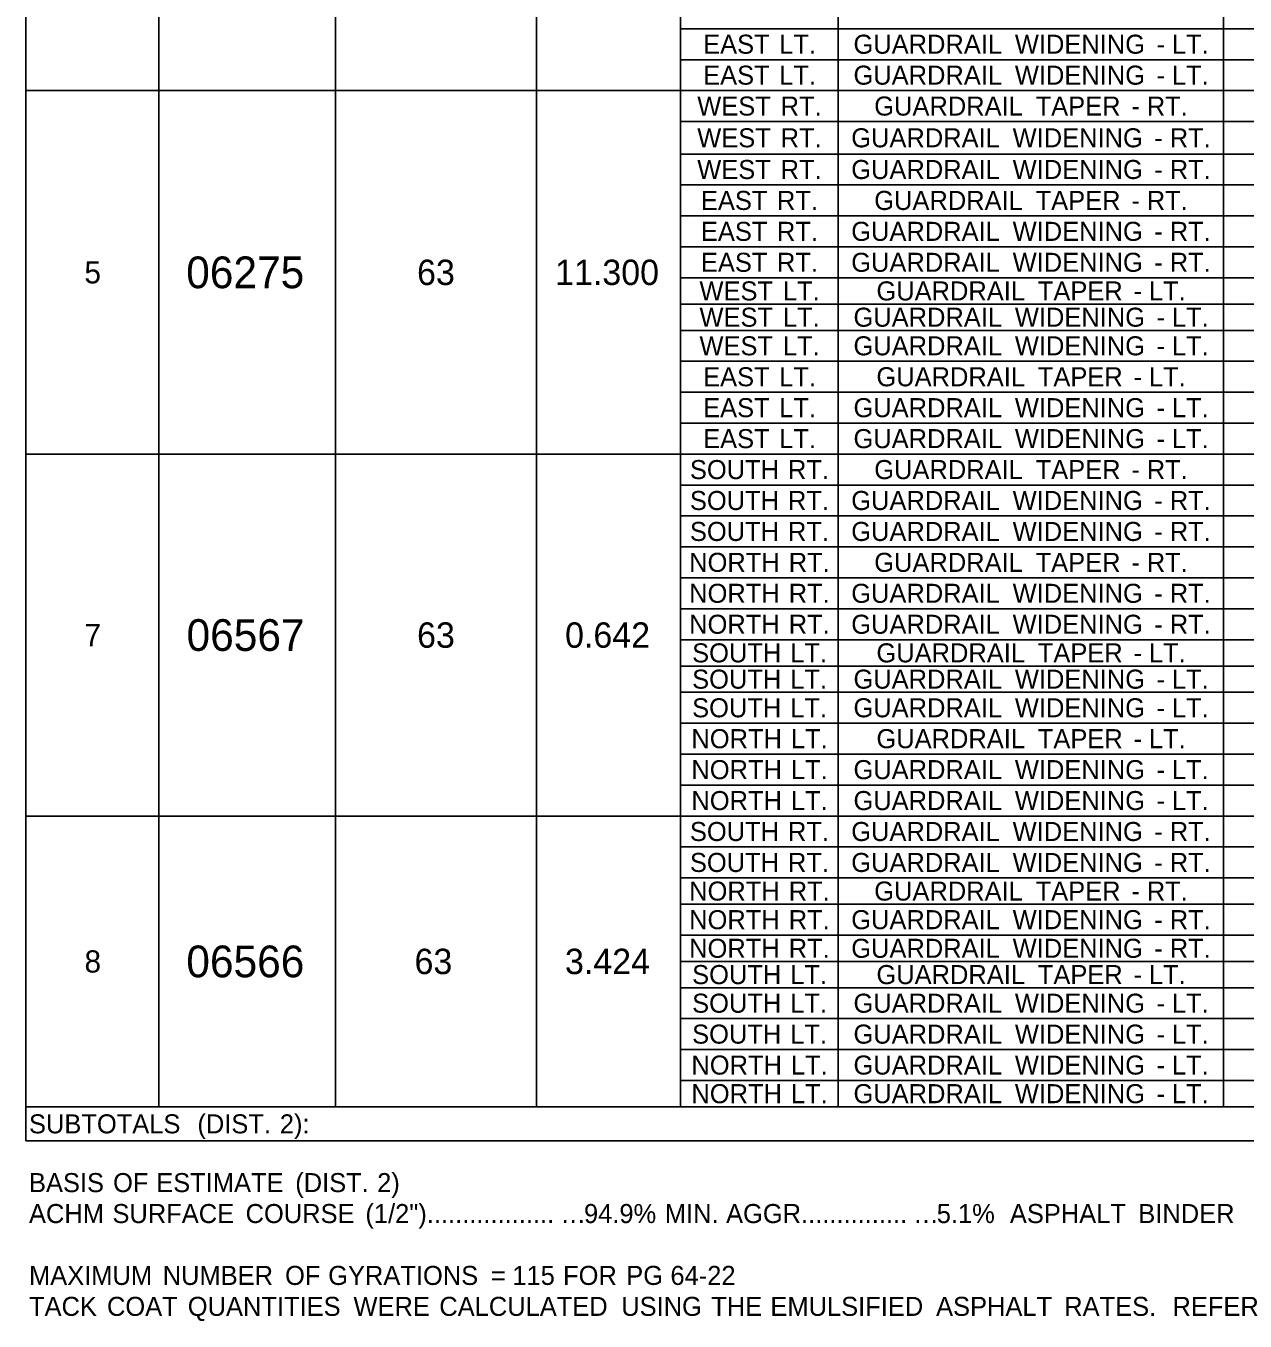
# Model space of a CAD drawing. Extents: x 544250 to 1930787, y -1948365 to 596640.
# Drawn here: x 555672.1 to 556001.3, y -1946822.7 to -1946472.9 of the extents above; entities that cross this region are included whole.
import ezdxf

# ---------------------------------------------------------------- set-up
doc = ezdxf.new("R2010")
doc.units = 0
doc.layers.add('Default', color=7, linetype='Continuous')

msp = doc.modelspace()

# ---------------------------------------------------------------- linework, layer by layer
at = {"layer": 'Default'}
for p, q in [((555672.13, -1946774.02), (555672.13, -1946131.03)), ((555708.06, -1946764.83), (555708.06, -1946131.03)), ((555755.69, -1946764.83), (555755.69, -1946131.03)), ((555810, -1946764.83), (555810, -1946131.03)), ((555848.86, -1946764.83), (555848.86, -1946131.03)), ((555891.47, -1946764.83), (555891.47, -1946131.03)), ((555995.5, -1946764.83), (555995.5, -1946131.03)), ((555848.86, -1946473.62), (556257.47, -1946473.62)), ((555848.86, -1946481.98), (556257.47, -1946481.98)), ((555672.13, -1946490.33), (556257.47, -1946490.33)), ((555848.86, -1946498.69), (556257.47, -1946498.69)), ((555848.86, -1946507.46), (556257.47, -1946507.46)), ((555848.86, -1946515.82), (556257.47, -1946515.82)), ((555848.86, -1946524.18), (556257.47, -1946524.18)), ((555848.86, -1946532.53), (556257.47, -1946532.53)), ((555848.86, -1946540.89), (556257.47, -1946540.89)), ((555848.86, -1946547.99), (556257.47, -1946547.99)), ((555848.86, -1946555.09), (556257.47, -1946555.09)), ((555848.86, -1946563.45), (556257.47, -1946563.45)), ((555848.86, -1946571.8), (556257.47, -1946571.8)), ((555848.86, -1946580.16), (556257.47, -1946580.16)), ((555672.13, -1946588.52), (556257.47, -1946588.52)), ((555848.86, -1946596.87), (556257.47, -1946596.87)), ((555848.86, -1946605.23), (556257.47, -1946605.23)), ((555848.86, -1946613.59), (556257.47, -1946613.59)), ((555848.86, -1946621.94), (556257.47, -1946621.94)), ((555848.86, -1946630.3), (556257.47, -1946630.3)), ((555848.86, -1946638.65), (556257.47, -1946638.65)), ((555848.86, -1946645.76), (556257.47, -1946645.76)), ((555848.86, -1946652.86), (556257.47, -1946652.86)), ((555848.86, -1946661.21), (556257.47, -1946661.21)), ((555848.86, -1946669.57), (556257.47, -1946669.57)), ((555848.86, -1946677.93), (556257.47, -1946677.93)), ((555672.13, -1946686.28), (556257.47, -1946686.28)), ((555848.86, -1946686.28), (556257.47, -1946686.28)), ((555848.86, -1946694.64), (556257.47, -1946694.64)), ((555848.86, -1946702.99), (556257.47, -1946702.99)), ((555848.86, -1946710.1), (556257.47, -1946710.1)), ((555848.86, -1946718.45), (556257.47, -1946718.45)), ((555848.86, -1946725.56), (556257.47, -1946725.56)), ((555848.86, -1946732.66), (556257.47, -1946732.66)), ((555848.86, -1946741.01), (556257.47, -1946741.01)), ((555848.86, -1946749.37), (556257.47, -1946749.37)), ((555848.86, -1946757.73), (556257.47, -1946757.73)), ((555672.13, -1946764.83), (556257.47, -1946764.83)), ((555672.13, -1946774.02), (556257.47, -1946774.02))]:
    msp.add_line(p, q, dxfattribs=at)

# ---------------------------------------------------------------- texts
for s, height, p in [('EAST', 5.142, (555854.98, -1946480.37)), (' LT.', 5.142, (555873.6, -1946480.37)), ('GUARDRAIL', 5.142, (555895.57, -1946480.37)), (' WIDENING', 5.142, (555937.24, -1946480.37)), (' LT.', 5.142, (555979.66, -1946480.37)), (' -', 5.142, (555975.5, -1946480.37)), ('EAST', 5.142, (555854.98, -1946488.73)), (' LT.', 5.142, (555873.6, -1946488.73)), ('GUARDRAIL', 5.142, (555895.57, -1946488.73)), (' WIDENING', 5.142, (555937.24, -1946488.73)), (' LT.', 5.142, (555979.66, -1946488.73)), (' -', 5.142, (555975.5, -1946488.73)), ('WEST', 5.142, (555853.39, -1946497.08)), (' RT.', 5.142, (555874, -1946497.08)), ('GUARDRAIL', 5.142, (555901.18, -1946497.08)), (' TAPER', 5.142, (555942.84, -1946497.08)), (' -', 5.142, (555968.7, -1946497.08)), (' RT.', 5.142, (555972.86, -1946497.08)), ('WEST', 5.142, (555853.39, -1946505.65)), (' RT.', 5.142, (555874, -1946505.65)), ('GUARDRAIL', 5.142, (555894.97, -1946505.65)), (' WIDENING', 5.142, (555936.64, -1946505.65)), (' RT.', 5.142, (555979.06, -1946505.65)), (' -', 5.142, (555974.9, -1946505.65)), ('WEST', 5.142, (555853.39, -1946514.21)), (' RT.', 5.142, (555874, -1946514.21)), ('GUARDRAIL', 5.142, (555894.97, -1946514.21)), (' WIDENING', 5.142, (555936.64, -1946514.21)), (' RT.', 5.142, (555979.06, -1946514.21)), (' -', 5.142, (555974.9, -1946514.21)), ('EAST', 5.142, (555854.38, -1946522.57)), (' RT.', 5.142, (555873.01, -1946522.57)), ('GUARDRAIL', 5.142, (555901.18, -1946522.57)), (' TAPER', 5.142, (555942.84, -1946522.57)), (' RT.', 5.142, (555972.86, -1946522.57)), (' -', 5.142, (555968.7, -1946522.57)), ('EAST', 5.142, (555854.38, -1946530.92)), (' RT.', 5.142, (555873.01, -1946530.92)), ('GUARDRAIL', 5.142, (555894.97, -1946530.92)), (' WIDENING', 5.142, (555936.64, -1946530.92)), (' RT.', 5.142, (555979.06, -1946530.92)), (' -', 5.142, (555974.9, -1946530.92)), ('5', 6, (555687.93, -1946542.42)), ('06275', 8.57, (555715.41, -1946543.71)), ('63', 6.856, (555777.74, -1946542.85)), ('11.300', 6.856, (555815.02, -1946542.85)), ('EAST', 5.142, (555854.38, -1946539.28)), (' RT.', 5.142, (555873.01, -1946539.28)), ('GUARDRAIL', 5.142, (555894.97, -1946539.28)), (' WIDENING', 5.142, (555936.64, -1946539.28)), (' -', 5.142, (555974.9, -1946539.28)), (' RT.', 5.142, (555979.06, -1946539.28)), ('WEST', 5.142, (555853.99, -1946547.01)), (' LT.', 5.142, (555874.6, -1946547.01)), ('GUARDRAIL', 5.142, (555901.77, -1946547.01)), (' TAPER', 5.142, (555943.44, -1946547.01)), (' LT.', 5.142, (555973.46, -1946547.01)), (' -', 5.142, (555969.3, -1946547.01)), ('WEST', 5.142, (555853.99, -1946554.11)), (' LT.', 5.142, (555874.6, -1946554.11)), ('GUARDRAIL', 5.142, (555895.57, -1946554.11)), (' WIDENING', 5.142, (555937.24, -1946554.11)), (' LT.', 5.142, (555979.66, -1946554.11)), (' -', 5.142, (555975.5, -1946554.11)), ('WEST', 5.142, (555853.99, -1946561.84)), (' LT.', 5.142, (555874.6, -1946561.84)), ('GUARDRAIL', 5.142, (555895.57, -1946561.84)), (' WIDENING', 5.142, (555937.24, -1946561.84)), (' LT.', 5.142, (555979.66, -1946561.84)), (' -', 5.142, (555975.5, -1946561.84)), ('EAST', 5.142, (555854.98, -1946570.2)), (' LT.', 5.142, (555873.6, -1946570.2)), ('GUARDRAIL', 5.142, (555901.77, -1946570.2)), (' TAPER', 5.142, (555943.44, -1946570.2)), (' LT.', 5.142, (555973.46, -1946570.2)), (' -', 5.142, (555969.3, -1946570.2)), ('EAST', 5.142, (555854.98, -1946578.55)), (' LT.', 5.142, (555873.6, -1946578.55)), ('GUARDRAIL', 5.142, (555895.57, -1946578.55)), (' WIDENING', 5.142, (555937.24, -1946578.55)), (' LT.', 5.142, (555979.66, -1946578.55)), (' -', 5.142, (555975.5, -1946578.55)), ('EAST', 5.142, (555854.98, -1946586.91)), (' LT.', 5.142, (555873.6, -1946586.91)), ('GUARDRAIL', 5.142, (555895.57, -1946586.91)), (' WIDENING', 5.142, (555937.24, -1946586.91)), (' LT.', 5.142, (555979.66, -1946586.91)), (' -', 5.142, (555975.5, -1946586.91)), ('SOUTH', 5.142, (555851.41, -1946595.27)), (' RT.', 5.142, (555875.98, -1946595.27)), ('GUARDRAIL', 5.142, (555901.18, -1946595.27)), (' TAPER', 5.142, (555942.84, -1946595.27)), (' -', 5.142, (555968.7, -1946595.27)), (' RT.', 5.142, (555972.86, -1946595.27)), ('SOUTH', 5.142, (555851.41, -1946603.62)), (' RT.', 5.142, (555875.98, -1946603.62)), ('GUARDRAIL', 5.142, (555894.97, -1946603.62)), (' WIDENING', 5.142, (555936.64, -1946603.62)), (' RT.', 5.142, (555979.06, -1946603.62)), (' -', 5.142, (555974.9, -1946603.62)), ('SOUTH', 5.142, (555851.41, -1946611.98)), (' RT.', 5.142, (555875.98, -1946611.98)), ('GUARDRAIL', 5.142, (555894.97, -1946611.98)), (' WIDENING', 5.142, (555936.64, -1946611.98)), (' RT.', 5.142, (555979.06, -1946611.98)), (' -', 5.142, (555974.9, -1946611.98)), ('NORTH', 5.142, (555851.21, -1946620.33)), (' RT.', 5.142, (555876.18, -1946620.33)), ('GUARDRAIL', 5.142, (555901.18, -1946620.33)), (' TAPER', 5.142, (555942.84, -1946620.33)), (' RT.', 5.142, (555972.86, -1946620.33)), (' -', 5.142, (555968.7, -1946620.33)), ('NORTH', 5.142, (555851.21, -1946628.69)), (' RT.', 5.142, (555876.18, -1946628.69)), ('GUARDRAIL', 5.142, (555894.97, -1946628.69)), (' WIDENING', 5.142, (555936.64, -1946628.69)), (' RT.', 5.142, (555979.06, -1946628.69)), (' -', 5.142, (555974.9, -1946628.69)), ('7', 6, (555687.95, -1946640.4)), ('06567', 8.57, (555715.5, -1946641.68)), ('63', 6.856, (555777.74, -1946640.83)), ('0.642', 6.856, (555817.7, -1946640.83)), ('NORTH', 5.142, (555851.21, -1946637.05)), (' RT.', 5.142, (555876.18, -1946637.05)), ('GUARDRAIL', 5.142, (555894.97, -1946637.05)), (' WIDENING', 5.142, (555936.64, -1946637.05)), (' -', 5.142, (555974.9, -1946637.05)), (' RT.', 5.142, (555979.06, -1946637.05)), ('SOUTH', 5.142, (555852.01, -1946644.78)), (' LT.', 5.142, (555876.58, -1946644.78)), ('GUARDRAIL', 5.142, (555901.77, -1946644.78)), (' TAPER', 5.142, (555943.44, -1946644.78)), (' LT.', 5.142, (555973.46, -1946644.78)), (' -', 5.142, (555969.3, -1946644.78)), ('SOUTH', 5.142, (555852.01, -1946651.88)), (' LT.', 5.142, (555876.58, -1946651.88)), ('GUARDRAIL', 5.142, (555895.57, -1946651.88)), (' WIDENING', 5.142, (555937.24, -1946651.88)), (' LT.', 5.142, (555979.66, -1946651.88)), (' -', 5.142, (555975.5, -1946651.88)), ('SOUTH', 5.142, (555852.01, -1946659.61)), (' LT.', 5.142, (555876.58, -1946659.61)), ('GUARDRAIL', 5.142, (555895.57, -1946659.61)), (' WIDENING', 5.142, (555937.24, -1946659.61)), (' LT.', 5.142, (555979.66, -1946659.61)), (' -', 5.142, (555975.5, -1946659.61)), ('NORTH', 5.142, (555851.81, -1946667.96)), (' LT.', 5.142, (555876.77, -1946667.96)), ('GUARDRAIL', 5.142, (555901.77, -1946667.96)), (' TAPER', 5.142, (555943.44, -1946667.96)), (' LT.', 5.142, (555973.46, -1946667.96)), (' -', 5.142, (555969.3, -1946667.96)), ('NORTH', 5.142, (555851.81, -1946676.32)), (' LT.', 5.142, (555876.77, -1946676.32)), ('GUARDRAIL', 5.142, (555895.57, -1946676.32)), (' WIDENING', 5.142, (555937.24, -1946676.32)), (' LT.', 5.142, (555979.66, -1946676.32)), (' -', 5.142, (555975.5, -1946676.32)), ('NORTH', 5.142, (555851.81, -1946684.68)), (' LT.', 5.142, (555876.77, -1946684.68)), ('GUARDRAIL', 5.142, (555895.57, -1946684.68)), (' WIDENING', 5.142, (555937.24, -1946684.68)), (' LT.', 5.142, (555979.66, -1946684.68)), (' -', 5.142, (555975.5, -1946684.68)), ('SOUTH', 5.142, (555851.41, -1946693.03)), (' RT.', 5.142, (555875.98, -1946693.03)), ('GUARDRAIL', 5.142, (555894.97, -1946693.03)), (' WIDENING', 5.142, (555936.64, -1946693.03)), (' -', 5.142, (555974.9, -1946693.03)), (' RT.', 5.142, (555979.06, -1946693.03)), ('SOUTH', 5.142, (555851.41, -1946701.39)), (' RT.', 5.142, (555875.98, -1946701.39)), ('GUARDRAIL', 5.142, (555894.97, -1946701.39)), (' WIDENING', 5.142, (555936.64, -1946701.39)), (' RT.', 5.142, (555979.06, -1946701.39)), (' -', 5.142, (555974.9, -1946701.39)), ('NORTH', 5.142, (555851.21, -1946709.12)), (' RT.', 5.142, (555876.18, -1946709.12)), ('GUARDRAIL', 5.142, (555901.18, -1946709.12)), (' TAPER', 5.142, (555942.84, -1946709.12)), (' RT.', 5.142, (555972.86, -1946709.12)), (' -', 5.142, (555968.7, -1946709.12)), ('NORTH', 5.142, (555851.21, -1946716.85)), (' RT.', 5.142, (555876.18, -1946716.85)), ('GUARDRAIL', 5.142, (555894.97, -1946716.85)), (' WIDENING', 5.142, (555936.64, -1946716.85)), (' RT.', 5.142, (555979.06, -1946716.85)), (' -', 5.142, (555974.9, -1946716.85)), ('8', 6, (555687.95, -1946728.56)), ('06566', 8.57, (555715.44, -1946729.84)), ('     63', 6.856, (555764.32, -1946728.98)), ('3.424', 6.856, (555817.68, -1946728.98)), ('NORTH', 5.142, (555851.21, -1946724.58)), (' RT.', 5.142, (555876.18, -1946724.58)), ('GUARDRAIL', 5.142, (555894.97, -1946724.58)), (' WIDENING', 5.142, (555936.64, -1946724.58)), (' -', 5.142, (555974.9, -1946724.58)), (' RT.', 5.142, (555979.06, -1946724.58)), ('SOUTH', 5.142, (555852.01, -1946731.68)), (' LT.', 5.142, (555876.58, -1946731.68)), ('GUARDRAIL', 5.142, (555901.77, -1946731.68)), (' TAPER', 5.142, (555943.44, -1946731.68)), (' -', 5.142, (555969.3, -1946731.68)), (' LT.', 5.142, (555973.46, -1946731.68)), ('SOUTH', 5.142, (555852.01, -1946739.41)), (' LT.', 5.142, (555876.58, -1946739.41)), ('GUARDRAIL', 5.142, (555895.57, -1946739.41)), (' WIDENING', 5.142, (555937.24, -1946739.41)), (' LT.', 5.142, (555979.66, -1946739.41)), (' -', 5.142, (555975.5, -1946739.41)), ('SOUTH', 5.142, (555852.01, -1946747.76)), (' LT.', 5.142, (555876.58, -1946747.76)), ('GUARDRAIL', 5.142, (555895.57, -1946747.76)), (' WIDENING', 5.142, (555937.24, -1946747.76)), (' LT.', 5.142, (555979.66, -1946747.76)), (' -', 5.142, (555975.5, -1946747.76)), ('NORTH', 5.142, (555851.81, -1946756.12)), (' LT.', 5.142, (555876.77, -1946756.12)), ('GUARDRAIL', 5.142, (555895.57, -1946756.12)), (' WIDENING', 5.142, (555937.24, -1946756.12)), (' -', 5.142, (555975.5, -1946756.12)), (' LT.', 5.142, (555979.66, -1946756.12)), ('NORTH', 5.142, (555851.81, -1946763.85)), (' LT.', 5.142, (555876.77, -1946763.85)), ('GUARDRAIL', 5.142, (555895.57, -1946763.85)), (' WIDENING', 5.142, (555937.24, -1946763.85)), (' LT.', 5.142, (555979.66, -1946763.85)), (' -', 5.142, (555975.5, -1946763.85)), ('SUBTOTALS', 5.142, (555672.96, -1946772)), (' (DIST.', 5.142, (555716.52, -1946772)), (' 2):', 5.142, (555738.78, -1946772)), ('BASIS', 5.142, (555672.96, -1946787.87)), (' OF', 5.142, (555693.75, -1946787.87)), (' ESTIMATE', 5.142, (555705.4, -1946787.87)), (' (DIST.', 5.142, (555742.94, -1946787.87)), (' 2)', 5.142, (555765.06, -1946787.87)), ('ACHM', 5.142, (555672.96, -1946796.23)), (' SURFACE', 5.142, (555693.58, -1946796.23)), (' COURSE', 5.142, (555729.53, -1946796.23)), (' (1/2")..................', 5.1422, (555761.88, -1946796.23)), ('94.9%', 5.142, (555822.81, -1946796.23)), (' MIN.', 5.142, (555842.73, -1946796.23)), (' AGGR...............', 5.1422, (555859.26, -1946796.23)), ('5.1%', 5.142, (555918.06, -1946796.23)), ('  ASPHALT', 5.142, (555933.98, -1946796.23)), (' BINDER', 5.142, (555970.57, -1946796.23)), ('…', 5.14, (555816.47, -1946796.23)), ('…', 5.14, (555911.72, -1946796.23)), ('MAXIMUM', 5.142, (555672.96, -1946812.94)), (' NUMBER', 5.142, (555707.15, -1946812.94)), (' OF', 5.142, (555740.18, -1946812.94)), (' GYRATIONS', 5.142, (555751.83, -1946812.94)), (' =', 5.142, (555795.77, -1946812.94)), (' 115', 5.142, (555801.56, -1946812.94)), (' FOR', 5.142, (555815.25, -1946812.94)), (' PG', 5.142, (555832.31, -1946812.94)), (' 64-22', 5.142, (555844.24, -1946812.94)), ('TACK', 5.142, (555672.96, -1946821.3)), (' COAT', 5.142, (555692.11, -1946821.3)), (' QUANTITIES', 5.1422, (555713.92, -1946821.3)), (' WERE', 5.142, (555758.66, -1946821.3)), (' CALCULATED', 5.1422, (555781.83, -1946821.3)), (' USING', 5.142, (555830.95, -1946821.3)), (' THE', 5.142, (555855.25, -1946821.3)), (' EMULSIFIED', 5.1422, (555871.23, -1946821.3)), (' ASPHALT', 5.142, (555915.96, -1946821.3)), (' RATES.', 5.142, (555950.56, -1946821.3)), ('  REFER', 5.142, (555977.88, -1946821.3))]:
    msp.add_text(s, height=height, dxfattribs=at).set_placement(p)

doc.saveas('drawing.dxf')
